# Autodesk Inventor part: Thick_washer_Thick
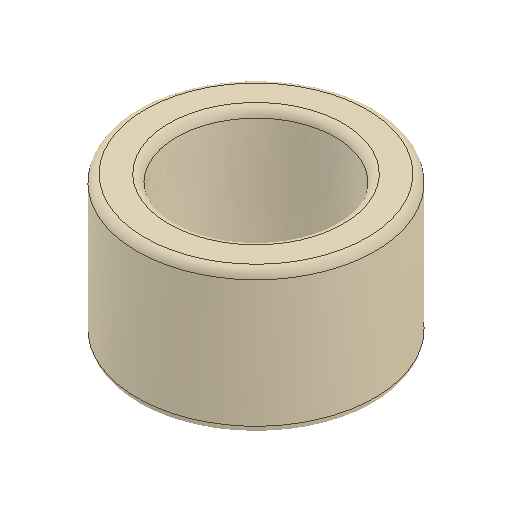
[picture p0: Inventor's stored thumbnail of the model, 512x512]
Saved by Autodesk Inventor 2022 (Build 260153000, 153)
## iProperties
Created: 2020-10
Part Number: Thick_washer_Thick
Material: Generico
Document SubType Name: Modeling
Designer: admin
Density: 1 g/cm^3
Appearance: Default
Author: admin
Sending System: SolidWorks 2020
Last Author: Simon
Last Saved: 2020-10-30
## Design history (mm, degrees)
fillet "Fillet1"
node "Solido1"
